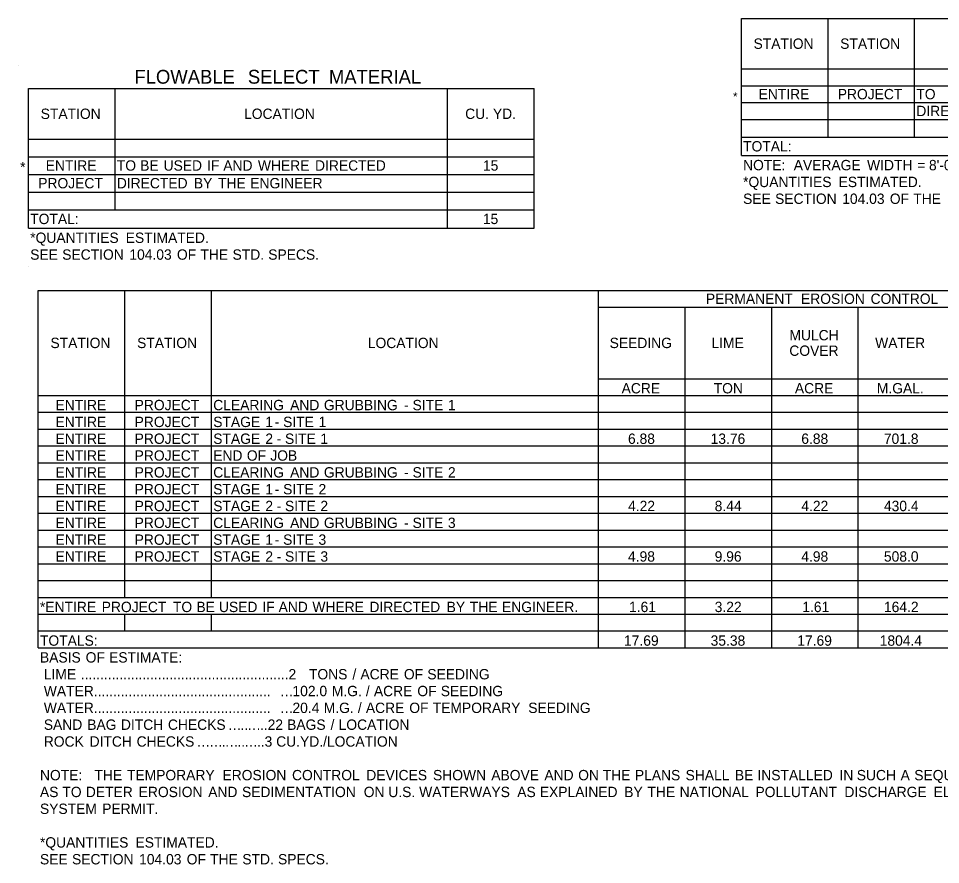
# Model space of a CAD drawing. Extents: x 977434 to 989596, y 1525697 to 1528336.
# Drawn here: x 980858 to 981393, y 1527353 to 1527844 of the extents above; entities that cross this region are included whole.
import ezdxf

# ---------------------------------------------------------------- set-up
doc = ezdxf.new("R2010")
doc.units = 0
doc.layers.add('Default', color=7, linetype='Continuous')
doc.layers.add('R_Border Prem', color=7, linetype='Continuous')

msp = doc.modelspace()

# ---------------------------------------------------------------- linework, layer by layer
at = {"layer": 'Default'}
for p, q in [((981277.44, 1527843.57), (981607.96, 1527843.57)), ((981277.44, 1527764.11), (981277.44, 1527843.57)), ((981277.44, 1527764.11), (981277.44, 1527843.57)), ((981327.65, 1527774.83), (981327.65, 1527843.57)), ((981377.86, 1527774.83), (981377.86, 1527843.57)), ((981277.44, 1527814.32), (981607.96, 1527814.32)), ((981327.65, 1527774.83), (981327.65, 1527814.32)), ((981377.86, 1527774.83), (981377.86, 1527814.32)), ((980864.24, 1527802.93), (981157.23, 1527802.93)), ((980864.24, 1527722.01), (980864.24, 1527802.93)), ((980864.24, 1527722.01), (980864.24, 1527802.93)), ((980914.46, 1527732.73), (980914.46, 1527802.93)), ((981107.02, 1527722.01), (981107.02, 1527802.93)), ((981157.23, 1527722.01), (981157.23, 1527802.93)), ((981157.23, 1527722.01), (981157.23, 1527802.93)), ((981277.44, 1527804.57), (981607.96, 1527804.57)), ((981277.44, 1527794.82), (981607.96, 1527794.82)), ((981277.44, 1527785.07), (981607.96, 1527785.07)), ((981277.44, 1527774.83), (981327.65, 1527774.83)), ((981277.44, 1527774.83), (981607.96, 1527774.83)), ((981327.65, 1527774.83), (981377.86, 1527774.83)), ((981377.86, 1527774.83), (981507.54, 1527774.83)), ((980864.24, 1527773.68), (981157.23, 1527773.68)), ((980914.46, 1527732.73), (980914.46, 1527773.68)), ((981107.02, 1527722.01), (981107.02, 1527773.68)), ((980864.24, 1527763.45), (981157.23, 1527763.45)), ((981277.44, 1527764.11), (981607.96, 1527764.11)), ((980864.24, 1527753.21), (981157.23, 1527753.21)), ((980864.24, 1527742.97), (981157.23, 1527742.97)), ((980864.24, 1527732.73), (981157.23, 1527732.73)), ((980864.24, 1527722.01), (981157.23, 1527722.01)), ((980869.9, 1527685.95), (982040.39, 1527685.95)), ((980869.9, 1527478.77), (980869.9, 1527685.95)), ((980869.9, 1527478.77), (980869.9, 1527685.95)), ((980920.11, 1527508.02), (980920.11, 1527685.95)), ((980970.32, 1527508.02), (980970.32, 1527685.95)), ((981194.57, 1527478.77), (981194.57, 1527685.95)), ((981194.57, 1527676.2), (982040.39, 1527676.2)), ((981244.79, 1527478.77), (981244.79, 1527676.2)), ((981295, 1527478.77), (981295, 1527676.2)), ((981345.21, 1527478.77), (981345.21, 1527676.2)), ((981194.57, 1527634.77), (982040.39, 1527634.77)), ((981244.79, 1527478.77), (981244.79, 1527634.77)), ((981295, 1527488.52), (981295, 1527634.77)), ((981345.21, 1527488.52), (981345.21, 1527634.77)), ((980869.9, 1527625.02), (982040.39, 1527625.02)), ((980920.11, 1527508.02), (980920.11, 1527625.02)), ((980970.32, 1527508.02), (980970.32, 1527625.02)), ((981194.57, 1527508.02), (981194.57, 1527625.02)), ((980869.9, 1527615.27), (982040.39, 1527615.27)), ((980869.9, 1527605.52), (982040.39, 1527605.52)), ((980869.9, 1527595.77), (982040.39, 1527595.77)), ((980869.9, 1527586.02), (982040.39, 1527586.02)), ((980869.9, 1527576.27), (982040.39, 1527576.27)), ((980869.9, 1527566.52), (982040.39, 1527566.52)), ((980869.9, 1527556.77), (982040.39, 1527556.77)), ((980869.9, 1527547.02), (982040.39, 1527547.02)), ((980869.9, 1527537.27), (982040.39, 1527537.27)), ((980869.9, 1527527.52), (982040.39, 1527527.52)), ((980869.9, 1527517.77), (982040.39, 1527517.77)), ((980869.9, 1527508.02), (982040.39, 1527508.02)), ((980869.9, 1527498.27), (982040.39, 1527498.27)), ((980920.11, 1527488.52), (980920.11, 1527498.27)), ((980920.11, 1527488.52), (980920.11, 1527498.27)), ((980970.32, 1527488.52), (980970.32, 1527498.27)), ((980970.32, 1527488.52), (980970.32, 1527498.27)), ((981194.57, 1527478.77), (981194.57, 1527498.27)), ((980869.9, 1527488.52), (981914.12, 1527488.52)), ((981244.79, 1527488.52), (981455.87, 1527488.52)), ((980869.9, 1527478.77), (982040.39, 1527478.77))]:
    msp.add_line(p, q, dxfattribs=at)
at = {"layer": 'R_Border Prem'}
for p, q in [((980858.39, 1527816.58), (980858.39, 1527816.58)), ((980864.05, 1527699.6), (980864.05, 1527699.6))]:
    msp.add_line(p, q, dxfattribs=at)

# ---------------------------------------------------------------- texts
at = {"layer": 'Default'}
for s, height, p in [('STATION', 6, (981284.48, 1527825.95)), ('STATION', 6, (981334.7, 1527825.95)), ('FLOWABLE', 8, (980925.6, 1527805.76)), (' SELECT', 8, (980988.38, 1527805.76)), (' MATERIAL', 8, (981035.36, 1527805.76)), ('*', 5, (981272.56, 1527795.82)), ('ENTIRE', 6, (981287.4, 1527796.7)), ('PROJECT', 6, (981333.28, 1527796.7)), ('TO', 6, (981378.84, 1527796.7)), ('STATION', 6, (980871.29, 1527785.31)), ('LOCATION', 6, (980989.18, 1527785.31)), ('CU.', 6, (981117.33, 1527785.31)), (' YD.', 6, (981131.19, 1527785.31)), ('DIRECTED', 6, (981378.84, 1527786.95)), ('TOTAL:', 6, (981278.41, 1527766.47)), ('*', 6, (980859.37, 1527754.41)), ('ENTIRE', 6, (980874.2, 1527755.33)), ('TO', 6, (980915.43, 1527755.33)), (' BE', 6, (980926.74, 1527755.33)), (' USED', 6, (980940.3, 1527755.33)), (' IF', 6, (980965.51, 1527755.33)), (' AND', 6, (980974.9, 1527755.33)), (' WHERE', 6, (980994.97, 1527755.33)), (' DIRECTED', 6, (981028.09, 1527755.33)), ('15', 6, (981127.63, 1527755.33)), ('NOTE:', 6, (981278.41, 1527755.56)), ('  AVERAGE', 6, (981303.3, 1527755.56)), (' WIDTH', 6, (981348.05, 1527755.56)), (' =', 6, (981377.17, 1527755.56)), (' 8\'-0"', 6, (981383.93, 1527755.56)), ('PROJECT', 6, (980869.87, 1527745.09)), ('DIRECTED', 6, (980915.43, 1527745.09)), (' BY', 6, (980957.87, 1527745.09)), (' THE', 6, (980971.86, 1527745.09)), (' ENGINEER', 6, (980990.54, 1527745.09)), ('*QUANTITIES', 6, (981278.41, 1527745.81)), (' ESTIMATED.', 6, (981331.54, 1527745.81)), ('SEE', 6, (981278.41, 1527736.06)), (' SECTION', 6, (981294.74, 1527736.06)), (' 104.03', 6, (981333.65, 1527736.06)), (' OF', 6, (981361.23, 1527736.06)), (' THE', 6, (981374.82, 1527736.06)), ('TOTAL:', 6, (980865.22, 1527724.37)), ('15', 6, (981127.59, 1527724.37)), ('*QUANTITIES', 6, (980865.22, 1527713.46)), (' ESTIMATED.', 6, (980918.35, 1527713.46)), ('SEE', 6, (980865.22, 1527703.71)), (' SECTION', 6, (980881.55, 1527703.71)), (' 104.03', 6, (980920.46, 1527703.71)), (' OF', 6, (980948.03, 1527703.71)), (' THE', 6, (980961.62, 1527703.71)), (' STD.', 6, (980980.27, 1527703.71)), (' SPECS.', 6, (981000.96, 1527703.71)), ('PERMANENT', 6, (981256.84, 1527678.08)), (' EROSION', 6, (981309.76, 1527678.08)), (' CONTROL', 6, (981350.09, 1527678.08)), ('MULCH', 6, (981305.29, 1527656.99)), ('STATION', 6, (980876.94, 1527652.49)), ('STATION', 6, (980927.16, 1527652.49)), ('LOCATION', 6, (981060.9, 1527652.49)), ('SEEDING', 6, (981201.07, 1527652.49)), ('LIME', 6, (981260.09, 1527652.49)), ('WATER', 6, (981354.97, 1527652.49)), ('COVER', 6, (981305.22, 1527647.99)), ('ACRE', 6, (981208.01, 1527626.22)), ('TON', 6, (981261.38, 1527626.22)), ('ACRE', 6, (981308.44, 1527626.22)), ('M.GAL.', 6, (981355.94, 1527626.22)), ('ENTIRE', 6, (980879.86, 1527616.47)), ('PROJECT', 6, (980925.74, 1527616.47)), ('CLEARING', 6, (980971.3, 1527616.47)), (' AND', 6, (981013.63, 1527616.47)), (' GRUBBING', 6, (981033.22, 1527616.47)), (' -', 6, (981079.74, 1527616.47)), (' SITE', 6, (981084.6, 1527616.47)), (' 1', 6, (981105.11, 1527616.47)), ('ENTIRE', 6, (980879.86, 1527606.72)), ('PROJECT', 6, (980925.74, 1527606.72)), ('STAGE', 6, (980971.3, 1527606.72)), (' 1', 6, (980999.27, 1527606.72)), (' -', 6, (981004.72, 1527606.72)), (' SITE', 6, (981009.58, 1527606.72)), (' 1', 6, (981030.09, 1527606.72)), ('PROJECT', 6, (980925.74, 1527596.97)), ('STAGE', 6, (980971.3, 1527596.97)), (' 2', 6, (980999.27, 1527596.97)), (' SITE', 6, (981010.67, 1527596.97)), ('6.88', 6, (981211.71, 1527596.97)), ('13.76', 6, (981259.6, 1527596.97)), ('6.88', 6, (981312.14, 1527596.97)), ('701.8', 6, (981360.02, 1527596.97)), ('ENTIRE', 6, (980879.86, 1527596.97)), (' -', 6, (981005.82, 1527596.97)), (' 1', 6, (981031.19, 1527596.97)), ('ENTIRE', 6, (980879.86, 1527587.22)), ('PROJECT', 6, (980925.74, 1527587.22)), ('END', 6, (980971.3, 1527587.22)), (' OF', 6, (980988.55, 1527587.22)), (' JOB', 6, (981002.14, 1527587.22)), ('ENTIRE', 6, (980879.86, 1527577.47)), ('PROJECT', 6, (980925.74, 1527577.47)), ('CLEARING', 6, (980971.3, 1527577.47)), (' AND', 6, (981013.63, 1527577.47)), (' GRUBBING', 6, (981033.22, 1527577.47)), (' SITE', 6, (981084.6, 1527577.47)), (' 2', 6, (981105.11, 1527577.47)), (' -', 6, (981079.74, 1527577.47)), ('ENTIRE', 6, (980879.86, 1527567.72)), ('PROJECT', 6, (980925.74, 1527567.72)), ('STAGE', 6, (980971.3, 1527567.72)), (' 1', 6, (980999.27, 1527567.72)), (' SITE', 6, (981009.58, 1527567.72)), (' 2', 6, (981030.09, 1527567.72)), (' -', 6, (981004.72, 1527567.72)), ('ENTIRE', 6, (980879.86, 1527557.97)), ('PROJECT', 6, (980925.74, 1527557.97)), ('STAGE', 6, (980971.3, 1527557.97)), (' 2', 6, (980999.27, 1527557.97)), (' -', 6, (981005.82, 1527557.97)), (' SITE', 6, (981010.67, 1527557.97)), (' 2', 6, (981031.19, 1527557.97)), ('4.22', 6, (981211.75, 1527557.97)), ('8.44', 6, (981261.94, 1527557.97)), ('4.22', 6, (981312.17, 1527557.97)), ('430.4', 6, (981360.04, 1527557.97)), ('ENTIRE', 6, (980879.86, 1527548.22)), ('PROJECT', 6, (980925.74, 1527548.22)), ('CLEARING', 6, (980971.3, 1527548.22)), (' AND', 6, (981013.63, 1527548.22)), (' GRUBBING', 6, (981033.22, 1527548.22)), (' -', 6, (981079.74, 1527548.22)), (' SITE', 6, (981084.6, 1527548.22)), (' 3', 6, (981105.11, 1527548.22)), ('ENTIRE', 6, (980879.86, 1527538.47)), ('PROJECT', 6, (980925.74, 1527538.47)), ('STAGE', 6, (980971.3, 1527538.47)), (' 1', 6, (980999.27, 1527538.47)), (' SITE', 6, (981009.58, 1527538.47)), (' 3', 6, (981030.09, 1527538.47)), (' -', 6, (981004.72, 1527538.47)), ('ENTIRE', 6, (980879.86, 1527528.72)), ('PROJECT', 6, (980925.74, 1527528.72)), ('STAGE', 6, (980971.3, 1527528.72)), (' 2', 6, (980999.27, 1527528.72)), (' SITE', 6, (981010.67, 1527528.72)), (' 3', 6, (981031.19, 1527528.72)), ('4.98', 6, (981211.71, 1527528.72)), ('9.96', 6, (981261.93, 1527528.72)), ('4.98', 6, (981312.14, 1527528.72)), ('508.0', 6, (981360.04, 1527528.72)), (' -', 6, (981005.82, 1527528.72)), ('*ENTIRE', 6, (980870.87, 1527499.47)), (' PROJECT', 6, (980904.43, 1527499.47)), (' TO', 6, (980945.72, 1527499.47)), (' BE', 6, (980959.32, 1527499.47)), (' USED', 6, (980972.39, 1527499.47)), (' IF', 6, (980997.56, 1527499.47)), (' AND', 6, (981006.95, 1527499.47)), (' WHERE', 6, (981026.54, 1527499.47)), (' DIRECTED', 6, (981059.62, 1527499.47)), (' BY', 6, (981104.36, 1527499.47)), (' THE', 6, (981117.81, 1527499.47)), (' ENGINEER.', 6, (981136.46, 1527499.47)), ('1.61', 6, (981212.3, 1527499.47)), ('3.22', 6, (981261.96, 1527499.47)), ('1.61', 6, (981312.72, 1527499.47)), ('164.2', 6, (981360.06, 1527499.47)), ('TOTALS:', 6, (980870.87, 1527479.97)), ('17.69', 6, (981209.39, 1527479.97)), ('35.38', 6, (981259.6, 1527479.97)), ('17.69', 6, (981309.82, 1527479.97)), ('1804.4', 6, (981357.6, 1527479.97)), ('BASIS', 6, (980870.87, 1527470.22)), (' OF', 6, (980895.14, 1527470.22)), (' ESTIMATE:', 6, (980908.72, 1527470.22)), (' LIME', 6, (980870.87, 1527460.47)), (' ......................................................2', 6, (980892.32, 1527460.47)), (' TONS', 6, (981024.56, 1527460.47)), (' /', 6, (981049.74, 1527460.47)), (' ACRE', 6, (981054.4, 1527460.47)), (' OF', 6, (981079.58, 1527460.47)), (' SEEDING', 6, (981093.16, 1527460.47)), (' WATER..............................................', 6, (980870.87, 1527450.72)), ('102.0', 6, (981017.22, 1527450.72)), (' M.G.', 6, (981037.79, 1527450.72)), (' /', 6, (981057.54, 1527450.72)), (' ACRE', 6, (981062.2, 1527450.72)), (' OF', 6, (981087.38, 1527450.72)), (' SEEDING', 6, (981100.96, 1527450.72)), ('…', 6, (981009.82, 1527450.72)), (' WATER..............................................', 6, (980870.87, 1527440.97)), ('20.4', 6, (981017.22, 1527440.97)), (' M.G.', 6, (981033.12, 1527440.97)), (' /', 6, (981052.88, 1527440.97)), (' ACRE', 6, (981057.54, 1527440.97)), (' OF', 6, (981082.71, 1527440.97)), (' TEMPORARY', 6, (981096.3, 1527440.97)), (' SEEDING', 6, (981151.67, 1527440.97)), (' SAND', 6, (980870.87, 1527431.22)), (' BAG', 6, (980896.05, 1527431.22)), (' DITCH', 6, (980915.56, 1527431.22)), (' CHECKS', 6, (980942.82, 1527431.22)), ('..22', 6, (980998.38, 1527431.22)), ('…', 6, (981009.82, 1527440.97)), (' BAGS', 6, (981011.91, 1527431.22)), (' /', 6, (981037.1, 1527431.22)), (' LOCATION', 6, (981041.76, 1527431.22)), ('…', 6, (980979.66, 1527431.22)), ('..', 6, (980987.06, 1527431.22)), ('…', 6, (980990.98, 1527431.22)), (' ROCK', 6, (980870.87, 1527421.47)), (' DITCH', 6, (980897.41, 1527421.47)), (' CHECKS', 6, (980924.67, 1527421.47)), ('..3', 6, (980996.62, 1527421.47)), (' CU.YD./LOCATION', 6, (981005.56, 1527421.47)), ('…', 6, (980961.51, 1527421.47)), ('…', 6, (980968.9, 1527421.47)), ('.', 6, (980976.3, 1527421.47)), ('…', 6, (980977.9, 1527421.47)), ('..', 6, (980985.3, 1527421.47)), ('…', 6, (980989.22, 1527421.47)), ('NOTE:', 6, (980870.87, 1527401.97)), ('   THE', 6, (980895.76, 1527401.97)), (' TEMPORARY', 6, (980919.07, 1527401.97)), (' EROSION', 6, (980974.44, 1527401.97)), (' CONTROL', 6, (981014.75, 1527401.97)), (' DEVICES', 6, (981057.77, 1527401.97)), (' SHOWN', 6, (981096.46, 1527401.97)), (' ABOVE', 6, (981130.24, 1527401.97)), (' AND', 6, (981161.01, 1527401.97)), (' ON', 6, (981180.6, 1527401.97)), (' THE', 6, (981194.82, 1527401.97)), (' PLANS', 6, (981213.46, 1527401.97)), (' SHALL', 6, (981242.85, 1527401.97)), (' BE', 6, (981271.44, 1527401.97)), (' INSTALLED', 6, (981284.5, 1527401.97)), (' IN', 6, (981332.04, 1527401.97)), (' SUCH', 6, (981342.07, 1527401.97)), (' A', 6, (981367.48, 1527401.97)), (' SEQUENCE', 6, (981375.41, 1527401.97)), ('AS', 6, (980870.87, 1527392.22)), (' TO', 6, (980881.62, 1527392.22)), (' DETER', 6, (980895.22, 1527392.22)), (' EROSION', 6, (980925.85, 1527392.22)), (' AND', 6, (980966.16, 1527392.22)), (' SEDIMENTATION', 6, (980985.74, 1527392.22)), (' ON', 6, (981056.32, 1527392.22)), (' U.S.', 6, (981070.54, 1527392.22)), (' WATERWAYS', 6, (981088.44, 1527392.22)), (' AS', 6, (981145.29, 1527392.22)), (' EXPLAINED', 6, (981158.37, 1527392.22)), (' BY', 6, (981207.31, 1527392.22)), (' THE', 6, (981220.76, 1527392.22)), (' NATIONAL', 6, (981239.41, 1527392.22)), (' POLLUTANT', 6, (981283.37, 1527392.22)), (' DISCHARGE', 6, (981334.9, 1527392.22)), (' ELIMINATION', 6, (981386.63, 1527392.22)), ('SYSTEM', 6, (980870.87, 1527382.47)), (' PERMIT.', 6, (980904.72, 1527382.47)), ('*QUANTITIES', 6, (980870.87, 1527362.97)), (' ESTIMATED.', 6, (980924.01, 1527362.97)), ('SEE', 6, (980870.87, 1527353.22)), (' SECTION', 6, (980887.21, 1527353.22)), (' 104.03', 6, (980926.11, 1527353.22)), (' OF', 6, (980953.69, 1527353.22)), (' THE', 6, (980967.28, 1527353.22)), (' STD.', 6, (980985.93, 1527353.22)), (' SPECS.', 6, (981006.62, 1527353.22))]:
    msp.add_text(s, height=height, dxfattribs=at).set_placement(p)

doc.saveas('drawing.dxf')
